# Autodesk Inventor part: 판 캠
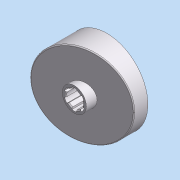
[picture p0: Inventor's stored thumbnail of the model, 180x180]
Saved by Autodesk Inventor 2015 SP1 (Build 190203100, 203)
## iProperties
Created: 2012-05
Part Number: 판 캠
Document SubType Name: 모델링
Designer: SeoGD™
Material: 강철
Appearance: 알루미늄 - 평지
Mass: 681.587 g
Surface Area: 331.303 cm^2
Volume: 86.8264 cm^3
Density: 7.85 g/cm^3
변환 표준: STEP AP214IS
파일 이름: C:\Users\SeoGD\Desktop\?쒗뿕\??stp
전처리기: Build: 253, Release: 2010 SP1 - Date: Wed 07/29/2009
전송 단위: 밀리미터
불확실성: 0.01
Author: SeoGD™
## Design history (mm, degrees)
node "작업 평면4"
sketch "스케치1"
  geometry: C1 r 44.5 at (0, 0); 1 further point
  constraints: 1 centre point, 1 coincident
  dimensions: "d25" = 89 diameter of C1
extrude "돌출1" new body sketch "스케치1" distance "d1" = 40; taper "d2" = 0 deg
sketch "스케치2"
  geometry: L1 (-44.5, 15)-(44.5, 38.847); L2 (-44.5, 0)-(-44.5, 40) reference; L3 (-44.5, 40)-(44.5, 40) reference; L4 (44.5, 0)-(44.5, 40) reference; 1 further point
  constraints: 2 end point, 2 point on line
  dimensions: "d26" = 15 distance of L2.start L1.start; "d27" = 75 deg angle of L1 L2
extrude "돌출2" cut sketch "스케치2" stored distance "d5" = 40; taper "d6" = 0 deg
node "작업 평면1"
sketch "스케치3"
  geometry: C1 r 13 at (0, 0); 1 further point
  constraints: 1 centre point, 1 coincident
  dimensions: "d9" = 26 diameter of C1
extrude "돌출3" join sketch "스케치3" distance "d10" = 38; taper "d11" = 0 deg
hole "구멍1" diameter "d14" = 18; stored, may be unused: countersink angle "d18" = 90 deg, drill point angle "d20" = 118 deg; dims "d12" = 10, "d13" = 10, "d15" = 6, "d16" = 4, "d17" = 2, "d19" = 8
feature "쉘2" dims "d29" = 5
sketch "스케치6"
  geometry: C1 r 17.5 at (0, 0); C2 r 14 at (0, 0) reference; 1 further point
  constraints: 1 centre point, 1 coincident
  dimensions: "d28" = 35 diameter of C1
extrude "돌출4" join sketch "스케치6" stored distance "d30" = 38; taper "d31" = 0 deg
fillet "모깎기1" dims "d32" = 3
chamfer "모따기1" distance "d21" = 1; stored, may be unused: second distance "d22" = 2, angle "d23" = 45 deg
sketch "스케치7"
  geometry: L1 (-12.374, 12.374)-(-27.931, 27.931); A1 r 39.5 centre (0, 0) between (-27.931, 27.931) and (0, 39.5) reference; 2 further points
  constraints: 2 end point, 2 point on circle, 1 point on line, 1 vertical alignment, 2 other
  dimensions: "d33" = 45 deg dimension on point (0, 0) L1.start A1.end
feature "리브1" sketch "스케치7" dims "d34" = 5, "d35" = 1, "d36" = 0
fillet "모깎기2" dims "d37" = 3
sketch "스케치8"
  geometry: L1 (2.5, 10.712)-(2.5, 8.646); L2 (-2.5, 10.712)-(-2.5, 8.646); A1 r 11 centre (0, 0) between (2.5, 10.712) and (-2.5, 10.712); A2 r 9 centre (0, 0) between (2.5, 8.646) and (-2.5, 8.646) reference; 1 further point
  constraints: 4 end point, 4 point on circle, 2 parallel, 1 centre point, 1 coincident, 1 vertical
  dimensions: "d41" = 22 diameter of A1; "d42" = 5 distance between parallel lines of L1 L2
extrude "돌출5" cut sketch "스케치8" stored distance "d43" = 38; taper "d44" = 0 deg
fillet "모깎기3" dims "d48" = 1
node "솔리드1"
node "솔리드 본체"
node "곡면 본체"
pattern_circular "원형 패턴1" dims angle "d39" = 360 deg
pattern_circular "원형 패턴2" dims angle "d46" = 360 deg
node "솔리드2"
